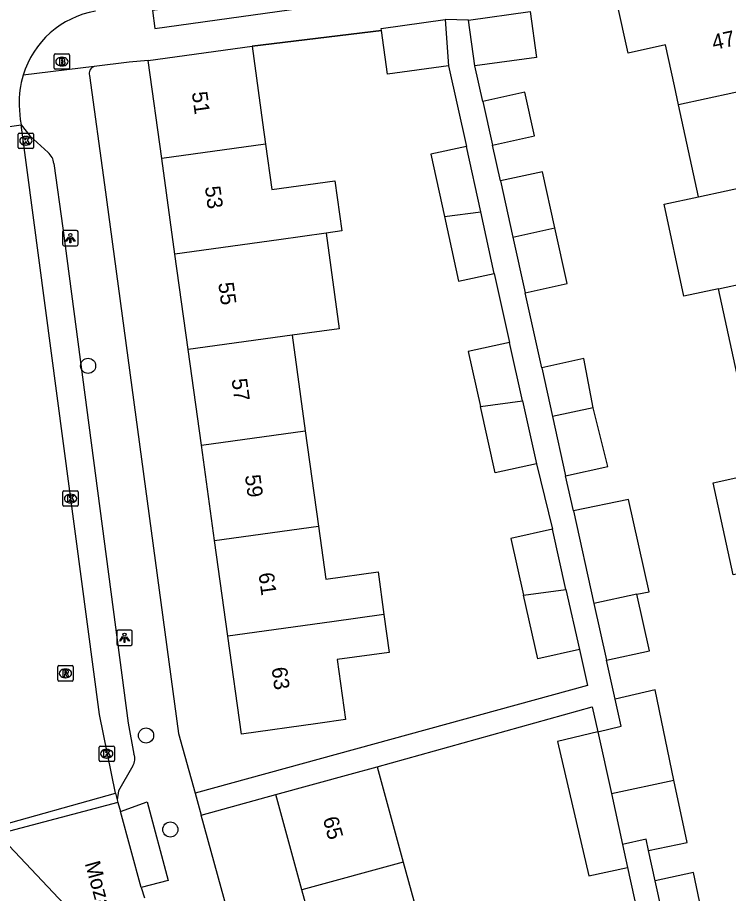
# Model space of a CAD drawing. Extents: x 159053 to 160041, y 380450 to 381422.
# Drawn here: x 159696.7 to 159742.8, y 380933.4 to 380990.2 of the extents above; entities that cross this region are included whole.
import ezdxf

# ---------------------------------------------------------------- set-up
doc = ezdxf.new("R2010")
doc.units = 0
for name, color, linetype in [('IMGEO_Boom', 7, 'Continuous'), ('IMGEO_Brandkraan', 7, 'Continuous'), ('IMGEO_Kolk', 7, 'Continuous'), ('IMGEO_Lichtpunt', 7, 'Continuous'), ('IMGEO_Muur', 7, 'Continuous'), ('IMGEO_Openbare_ruimte_label', 7, 'Continuous'), ('IMGEO_Pand', 7, 'Continuous'), ('IMGEO_Pand_nummerreeks', 7, 'Continuous'), ('IMGEO_Rijbaan_lokaal_open', 7, 'Continuous'), ('IMGEO_Rioolput', 7, 'Continuous'), ('IMGEO_Voetpad_op_trap', 7, 'Continuous'), ('IMGEO_Voetpad_open', 7, 'Continuous')]:
    doc.layers.add(name, color=color, linetype=linetype)

msp = doc.modelspace()

# ---------------------------------------------------------------- linework, layer by layer
at = {"layer": 'IMGEO_Boom'}
for centre in [(159701.274, 380967.567), (159705.031, 380943.603), (159706.604, 380937.507)]:
    msp.add_circle(centre, 0.489, dxfattribs=at)
at = {"layer": 'IMGEO_Brandkraan'}
for p, q in [((159699.148, 380987.793), (159700, 380987.793)), ((159699.073, 380986.867), (159699.073, 380987.719)), ((159699.561, 380987.573), (159699.586, 380987.573)), ((159700.074, 380987.719), (159700.074, 380986.867)), ((159700, 380986.793), (159699.148, 380986.793)), ((159699.584, 380987.013), (159699.559, 380987.013))]:
    msp.add_line(p, q, dxfattribs=at)
for points in [[(159699.148, 380987.793), (159700, 380987.793)], [(159699.073, 380986.867), (159699.073, 380987.719)], [(159699.421, 380987.493), (159699.421, 380987.093), (159699.634, 380987.093)], [(159699.652, 380987.493), (159699.421, 380987.493)], [(159699.6, 380987.412), (159699.546, 380987.412), (159699.546, 380987.336)], [(159699.546, 380987.336), (159699.599, 380987.336)], [(159699.608, 380987.26), (159699.546, 380987.26), (159699.546, 380987.179)], [(159699.546, 380987.179), (159699.608, 380987.179)], [(159700.074, 380987.719), (159700.074, 380986.867)], [(159700, 380986.793), (159699.148, 380986.793)]]:
    msp.add_lwpolyline(points, dxfattribs=at)
for centre, radius, start, end in [((159699.15, 380987.717), 0.0765, 91.552, 178.448), ((159699.15, 380987.717), 0.0765, 91.552, 178.448), ((159699.998, 380987.717), 0.0765, 1.552, 88.448), ((159699.998, 380987.717), 0.0765, 1.552, 88.448), ((159699.601, 380987.374), 0.0379, 267.8285, 90.9355), ((159699.609, 380987.219), 0.0404, 269.8759, 90.5077), ((159699.656, 380987.348), 0.145, 59.4692, 91.5367), ((159699.681, 380987.395), 0.0922, 285.5137, 58.1501), ((159699.686, 380987.203), 0.105, 301.3115, 78.989), ((159699.15, 380986.869), 0.0765, 181.552, 268.448), ((159699.15, 380986.869), 0.0765, 181.552, 268.448), ((159699.64, 380987.344), 0.251, 268.6676, 293.5347), ((159699.998, 380986.869), 0.0765, 271.552, 358.448), ((159699.998, 380986.869), 0.0765, 271.552, 358.448)]:
    msp.add_arc(centre, radius, start, end, dxfattribs=at)
for centre, major_axis, ratio, start_param, end_param in [((159699.56, 380987.293), (-0.387, 0.002), 0.722429, 4.712389, 7.853982), ((159699.585, 380987.293), (-0.39, 0.002), 0.717154, 1.570796, 4.712389)]:
    msp.add_ellipse(centre, major_axis=major_axis, ratio=ratio, start_param=start_param, end_param=end_param, dxfattribs=at)
at = {"layer": 'IMGEO_Kolk'}
for p, q in [((159696.813, 380982.66), (159697.665, 380982.66)), ((159696.738, 380981.734), (159696.738, 380982.586)), ((159697.226, 380982.44), (159697.251, 380982.44)), ((159697.739, 380982.586), (159697.739, 380981.734)), ((159697.665, 380981.66), (159696.813, 380981.66)), ((159697.249, 380981.88), (159697.224, 380981.88)), ((159699.635, 380958.538), (159699.635, 380959.39)), ((159699.71, 380959.464), (159700.562, 380959.464)), ((159700.636, 380959.39), (159700.636, 380958.538)), ((159700.123, 380959.244), (159700.148, 380959.244)), ((159700.562, 380958.464), (159699.71, 380958.464)), ((159700.146, 380958.684), (159700.121, 380958.684)), ((159702.056, 380942.921), (159702.908, 380942.921)), ((159701.981, 380941.995), (159701.981, 380942.847)), ((159702.469, 380942.701), (159702.494, 380942.701)), ((159702.982, 380942.847), (159702.982, 380941.995)), ((159702.908, 380941.921), (159702.056, 380941.921)), ((159702.492, 380942.141), (159702.467, 380942.141))]:
    msp.add_line(p, q, dxfattribs=at)
for points in [[(159696.813, 380982.66), (159697.665, 380982.66)], [(159696.738, 380981.734), (159696.738, 380982.586)], [(159697.059, 380982.36), (159697.182, 380982.36), (159697.182, 380982.209), (159697.312, 380982.36), (159697.476, 380982.36), (159697.33, 380982.209), (159697.483, 380981.96), (159697.331, 380981.96), (159697.246, 380982.124), (159697.182, 380982.057), (159697.182, 380981.96), (159697.059, 380981.96), (159697.059, 380982.36)], [(159697.739, 380982.586), (159697.739, 380981.734)], [(159697.665, 380981.66), (159696.813, 380981.66)], [(159699.635, 380958.538), (159699.635, 380959.39)], [(159699.71, 380959.464), (159700.562, 380959.464)], [(159700.636, 380959.39), (159700.636, 380958.538)], [(159699.956, 380959.164), (159700.079, 380959.164), (159700.079, 380959.013), (159700.209, 380959.164), (159700.373, 380959.164), (159700.227, 380959.013), (159700.38, 380958.764), (159700.228, 380958.764), (159700.143, 380958.928), (159700.079, 380958.861), (159700.079, 380958.764), (159699.956, 380958.764), (159699.956, 380959.164)], [(159700.562, 380958.464), (159699.71, 380958.464)], [(159702.056, 380942.921), (159702.908, 380942.921)], [(159701.981, 380941.995), (159701.981, 380942.847)], [(159702.302, 380942.621), (159702.425, 380942.621), (159702.425, 380942.47), (159702.555, 380942.621), (159702.719, 380942.621), (159702.573, 380942.47), (159702.726, 380942.221), (159702.574, 380942.221), (159702.489, 380942.385), (159702.425, 380942.318), (159702.425, 380942.221), (159702.302, 380942.221), (159702.302, 380942.621)], [(159702.982, 380942.847), (159702.982, 380941.995)], [(159702.908, 380941.921), (159702.056, 380941.921)]]:
    msp.add_lwpolyline(points, dxfattribs=at)
for centre, start, end in [((159696.815, 380982.584), 91.552, 178.448), ((159696.815, 380982.584), 91.552, 178.448), ((159697.663, 380982.584), 1.552, 88.448), ((159697.663, 380982.584), 1.552, 88.448), ((159696.815, 380981.736), 181.552, 268.448), ((159696.815, 380981.736), 181.552, 268.448), ((159697.663, 380981.736), 271.552, 358.448), ((159697.663, 380981.736), 271.552, 358.448), ((159699.712, 380959.388), 91.552, 178.448), ((159699.712, 380959.388), 91.552, 178.448), ((159700.56, 380959.388), 1.552, 88.448), ((159700.56, 380959.388), 1.552, 88.448), ((159699.712, 380958.54), 181.552, 268.448), ((159699.712, 380958.54), 181.552, 268.448), ((159700.56, 380958.54), 271.552, 358.448), ((159700.56, 380958.54), 271.552, 358.448), ((159702.058, 380942.845), 91.552, 178.448), ((159702.058, 380942.845), 91.552, 178.448), ((159702.906, 380942.845), 1.552, 88.448), ((159702.906, 380942.845), 1.552, 88.448), ((159702.058, 380941.997), 181.552, 268.448), ((159702.058, 380941.997), 181.552, 268.448), ((159702.906, 380941.997), 271.552, 358.448), ((159702.906, 380941.997), 271.552, 358.448)]:
    msp.add_arc(centre, 0.0765, start, end, dxfattribs=at)
for centre, major_axis, ratio, start_param, end_param in [((159697.225, 380982.16), (-0.387, 0.002), 0.722429, 4.712389, 7.853982), ((159697.25, 380982.16), (-0.39, 0.002), 0.717154, 1.570796, 4.712389), ((159700.122, 380958.964), (-0.387, 0.002), 0.722429, 4.712389, 7.853982), ((159700.147, 380958.964), (-0.39, 0.002), 0.717154, 1.570796, 4.712389), ((159702.468, 380942.421), (-0.387, 0.002), 0.722429, 4.712389, 7.853982), ((159702.493, 380942.421), (-0.39, 0.002), 0.717154, 1.570796, 4.712389)]:
    msp.add_ellipse(centre, major_axis=major_axis, ratio=ratio, start_param=start_param, end_param=end_param, dxfattribs=at)
at = {"layer": 'IMGEO_Lichtpunt'}
for p, q in [((159699.624, 380976.255), (159699.624, 380975.448)), ((159699.624, 380976.255), (159699.624, 380975.448)), ((159700.526, 380976.35), (159699.718, 380976.35)), ((159700.526, 380976.35), (159699.718, 380976.35)), ((159700.62, 380975.448), (159700.62, 380976.255)), ((159700.62, 380975.448), (159700.62, 380976.255)), ((159699.718, 380975.354), (159700.526, 380975.354)), ((159699.718, 380975.354), (159700.526, 380975.354)), ((159703.136, 380950.347), (159703.136, 380949.54)), ((159703.136, 380950.347), (159703.136, 380949.54)), ((159704.038, 380950.442), (159703.23, 380950.442)), ((159704.038, 380950.442), (159703.23, 380950.442)), ((159704.132, 380949.54), (159704.132, 380950.347)), ((159704.132, 380949.54), (159704.132, 380950.347)), ((159703.23, 380949.446), (159704.038, 380949.446)), ((159703.23, 380949.446), (159704.038, 380949.446))]:
    msp.add_line(p, q, dxfattribs=at)
for points in [[(159699.998, 380975.919), (159700.037, 380975.891), (159699.849, 380975.629), (159699.811, 380975.656), (159699.998, 380975.919)], [(159700.1, 380975.871), (159700.147, 380975.871), (159700.147, 380975.549), (159700.1, 380975.549), (159700.1, 380975.871)], [(159700.21, 380975.891), (159700.248, 380975.918), (159700.435, 380975.656), (159700.396, 380975.628), (159700.21, 380975.891)], [(159703.51, 380950.011), (159703.549, 380949.983), (159703.361, 380949.721), (159703.323, 380949.748), (159703.51, 380950.011)], [(159703.612, 380949.963), (159703.659, 380949.963), (159703.659, 380949.641), (159703.612, 380949.641), (159703.612, 380949.963)], [(159703.722, 380949.983), (159703.76, 380950.01), (159703.947, 380949.748), (159703.908, 380949.72), (159703.722, 380949.983)]]:
    msp.add_lwpolyline(points, dxfattribs=at)
for centre in [(159700.123, 380976.053), (159703.635, 380950.145)]:
    msp.add_circle(centre, 0.0994, dxfattribs=at)
for centre, start, end in [((159699.718, 380976.255), 90, 180), ((159699.718, 380976.255), 90, 180), ((159700.526, 380976.255), 0, 90), ((159700.526, 380976.255), 0, 90), ((159699.718, 380975.448), 180, 270), ((159699.718, 380975.448), 180, 270), ((159700.526, 380975.448), 270, 0), ((159700.526, 380975.448), 270, 360), ((159703.23, 380950.347), 90, 180), ((159703.23, 380950.347), 90, 180), ((159704.038, 380950.347), 0, 90), ((159704.038, 380950.347), 0, 90), ((159703.23, 380949.54), 180, 270), ((159703.23, 380949.54), 180, 270), ((159704.038, 380949.54), 270, 0), ((159704.038, 380949.54), 270, 360)]:
    msp.add_arc(centre, 0.0946, start, end, dxfattribs=at)
at = {"layer": 'IMGEO_Muur'}
msp.add_lwpolyline([(159711.9, 380988.291), (159720.286, 380989.3)], dxfattribs=at)
at = {"layer": 'IMGEO_Pand'}
for points in [[(159739.552, 380984.501), (159739.286, 380985.726), (159738.711, 380988.373), (159736.275, 380987.844), (159735.575, 380991.069)], [(159720.286, 380989.3), (159720.266, 380989.448), (159724.421, 380990.024)], [(159724.421, 380990.024), (159724.629, 380987.027)], [(159725.935, 380989.984), (159729.922, 380990.537)], [(159729.922, 380990.537), (159730.334, 380987.565), (159726.347, 380987.012)], [(159726.347, 380987.012), (159725.935, 380989.984)], [(159724.629, 380987.027), (159720.677, 380986.479), (159720.286, 380989.3)], [(159705.163, 380987.357), (159711.9, 380988.291)], [(159711.9, 380988.291), (159712.586, 380983.339), (159712.779, 380981.944)], [(159706.043, 380981.012), (159705.163, 380987.357)], [(159746.717, 380986.057), (159739.552, 380984.501)], [(159727.483, 380981.88), (159730.217, 380982.474), (159729.589, 380985.311), (159726.857, 380984.707)], [(159726.857, 380984.707), (159727.483, 380981.88)], [(159740.848, 380978.534), (159739.552, 380984.501)], [(159712.779, 380981.944), (159706.043, 380981.012)], [(159712.779, 380981.944), (159713.187, 380979.003), (159717.275, 380979.57), (159717.727, 380976.314), (159716.701, 380976.172)], [(159725.805, 380981.789), (159723.495, 380981.288), (159724.372, 380977.241)], [(159726.722, 380977.557), (159725.805, 380981.789)], [(159706.901, 380974.818), (159706.043, 380981.012)], [(159731.537, 380976.513), (159730.732, 380980.147), (159727.998, 380979.553)], [(159740.848, 380978.534), (159748.013, 380980.089)], [(159727.998, 380979.553), (159728.802, 380975.92)], [(159742.145, 380972.566), (159739.902, 380972.079), (159738.607, 380978.048), (159740.848, 380978.534)], [(159724.372, 380977.241), (159726.722, 380977.557)], [(159727.588, 380973.566), (159726.722, 380977.557)], [(159724.372, 380977.241), (159725.277, 380973.065), (159727.588, 380973.566)], [(159728.802, 380975.92), (159731.537, 380976.513)], [(159729.602, 380972.306), (159732.334, 380972.911), (159731.537, 380976.513)], [(159716.701, 380976.172), (159713.638, 380975.749), (159706.901, 380974.818)], [(159716.701, 380976.172), (159717.557, 380969.978), (159714.497, 380969.555)], [(159728.802, 380975.92), (159729.602, 380972.306)], [(159707.76, 380968.624), (159706.901, 380974.818)], [(159742.145, 380972.566), (159749.309, 380974.122)], [(159743.441, 380966.598), (159742.145, 380972.566)], [(159714.497, 380969.555), (159707.76, 380968.624)], [(159714.497, 380969.555), (159715.356, 380963.361)], [(159728.601, 380969.085), (159725.914, 380968.49), (159726.702, 380964.929)], [(159729.437, 380965.307), (159728.601, 380969.085)], [(159708.618, 380962.43), (159707.76, 380968.624)], [(159734.01, 380964.856), (159733.408, 380968.034), (159730.682, 380967.431)], [(159730.682, 380967.431), (159731.378, 380964.285)], [(159726.702, 380964.929), (159729.437, 380965.307)], [(159729.437, 380965.307), (159730.343, 380961.217)], [(159730.343, 380961.217), (159727.656, 380960.622), (159726.702, 380964.929)], [(159734.01, 380964.856), (159731.378, 380964.285)], [(159732.229, 380960.439), (159734.955, 380961.043), (159734.01, 380964.856)], [(159731.378, 380964.285), (159732.229, 380960.439)], [(159708.618, 380962.43), (159715.356, 380963.361)], [(159715.356, 380963.361), (159716.214, 380957.168)], [(159709.477, 380956.236), (159708.618, 380962.43)], [(159746.034, 380954.663), (159743.095, 380954.025), (159741.799, 380959.992), (159744.737, 380960.63)], [(159736.835, 380952.761), (159737.641, 380952.925), (159736.306, 380958.897), (159732.731, 380958.173)], [(159732.731, 380958.173), (159734.062, 380952.161)], [(159709.477, 380956.236), (159716.214, 380957.168)], [(159716.214, 380957.168), (159716.689, 380953.741), (159720.069, 380954.208), (159720.451, 380951.441)], [(159731.369, 380956.984), (159728.672, 380956.38), (159729.5, 380952.691)], [(159732.247, 380953.071), (159731.369, 380956.984)], [(159710.335, 380950.043), (159709.477, 380956.236)], [(159729.5, 380952.691), (159732.247, 380953.071)], [(159733.118, 380949.189), (159730.421, 380948.584), (159729.5, 380952.691)], [(159732.247, 380953.071), (159733.118, 380949.189)], [(159736.835, 380952.761), (159734.062, 380952.161)], [(159734.876, 380948.482), (159737.657, 380949.097), (159736.835, 380952.761)], [(159734.062, 380952.161), (159734.876, 380948.482)], [(159720.451, 380951.441), (159720.79, 380948.994), (159717.412, 380948.527), (159717.952, 380944.632), (159716.168, 380944.385), (159711.215, 380943.698), (159710.335, 380950.043)], [(159720.451, 380951.441), (159717.073, 380950.974), (159710.335, 380950.043)], [(159739.254, 380940.715), (159738.025, 380946.557), (159735.434, 380945.961)], [(159734.317, 380943.842), (159735.823, 380944.207), (159735.434, 380945.961)], [(159734.317, 380943.842), (159731.707, 380943.207), (159733.734, 380934.508), (159736.238, 380935.055)], [(159734.317, 380943.842), (159735.195, 380939.834)], [(159713.436, 380939.77), (159718.257, 380941.097), (159720.003, 380941.578)], [(159720.003, 380941.578), (159721.703, 380935.401)], [(159735.195, 380939.834), (159739.254, 380940.715)], [(159737.607, 380936.148), (159740.104, 380936.673), (159739.254, 380940.715)], [(159715.136, 380933.596), (159713.436, 380939.77)], [(159735.195, 380939.834), (159735.912, 380936.545)], [(159737.607, 380936.148), (159737.444, 380936.885), (159735.912, 380936.545)], [(159735.912, 380936.545), (159736.238, 380935.055)], [(159721.703, 380935.401), (159715.136, 380933.596)], [(159721.703, 380935.401), (159723.364, 380929.371)], [(159741.772, 380928.74), (159740.515, 380934.717), (159738.043, 380934.18)], [(159739.362, 380928.217), (159738.043, 380934.18)], [(159716.796, 380927.565), (159715.136, 380933.596)]]:
    msp.add_lwpolyline(points, dxfattribs=at)
at = {"layer": 'IMGEO_Rijbaan_lokaal_open'}
for points in [[(159696.805, 380984.452), (159696.873, 380983.547), (159696.938, 380983.189)], [(159692.329, 380982.539), (159696.938, 380983.189)], [(159703.047, 380939.869), (159702.009, 380944.971), (159696.938, 380983.189)], [(159695.017, 380937.616), (159703.047, 380939.869)], [(159703.047, 380939.869), (159703.16, 380939.431)], [(159703.204, 380939.257), (159695.431, 380937.204)], [(159703.16, 380939.431), (159703.204, 380939.257)], [(159703.204, 380939.257), (159703.364, 380938.667)], [(159704.723, 380933.738), (159703.364, 380938.667)], [(159700.436, 380931.909), (159695.431, 380937.204)], [(159704.723, 380933.738), (159704.926, 380933.073)]]:
    msp.add_lwpolyline(points, dxfattribs=at)
for centre, radius, start, end in [((159702.783, 380984.673), 5.982, 99.9432, 163.1371), ((159702.755, 380984.677), 5.954, 163.0959, 182.164)]:
    msp.add_arc(centre, radius, start, end, dxfattribs=at)
at = {"layer": 'IMGEO_Rioolput'}
for p, q in [((159699.305, 380947.205), (159699.305, 380948.057)), ((159699.38, 380948.131), (159700.232, 380948.131)), ((159700.306, 380948.057), (159700.306, 380947.205)), ((159699.793, 380947.911), (159699.818, 380947.911)), ((159700.232, 380947.131), (159699.38, 380947.131)), ((159699.816, 380947.351), (159699.791, 380947.351))]:
    msp.add_line(p, q, dxfattribs=at)
for points in [[(159699.305, 380947.205), (159699.305, 380948.057)], [(159699.38, 380948.131), (159700.232, 380948.131)], [(159700.306, 380948.057), (159700.306, 380947.205)], [(159699.894, 380947.829), (159699.642, 380947.831), (159699.642, 380947.431)], [(159699.642, 380947.431), (159699.766, 380947.431), (159699.766, 380947.593), (159699.777, 380947.593)], [(159699.82, 380947.75), (159699.766, 380947.75), (159699.766, 380947.669)], [(159699.766, 380947.669), (159699.818, 380947.669)], [(159699.824, 380947.564), (159699.895, 380947.431), (159700.035, 380947.431), (159699.97, 380947.557)], [(159700.232, 380947.131), (159699.38, 380947.131)]]:
    msp.add_lwpolyline(points, dxfattribs=at)
for centre, radius, start, end in [((159699.382, 380948.055), 0.0765, 91.552, 178.448), ((159699.382, 380948.055), 0.0765, 91.552, 178.448), ((159700.23, 380948.055), 0.0765, 1.552, 88.448), ((159700.23, 380948.055), 0.0765, 1.552, 88.448), ((159699.776, 380947.54), 0.0533, 26.0293, 88.6989), ((159699.802, 380947.858), 0.19, 274.7715, 282.9687), ((159699.826, 380947.654), 0.0964, 77.0061, 93.1865), ((159699.84, 380947.711), 0.0378, 276.6634, 79.6772), ((159699.893, 380947.719), 0.109, 350.3612, 89.416), ((159699.891, 380947.719), 0.112, 277.5842, 350.9817), ((159699.875, 380947.504), 0.108, 29.5134, 73.7905), ((159699.382, 380947.207), 0.0765, 181.552, 268.448), ((159699.382, 380947.207), 0.0765, 181.552, 268.448), ((159700.23, 380947.207), 0.0765, 271.552, 358.448), ((159700.23, 380947.207), 0.0765, 271.552, 358.448)]:
    msp.add_arc(centre, radius, start, end, dxfattribs=at)
for centre, major_axis, ratio, start_param, end_param in [((159699.792, 380947.631), (-0.387, 0.002), 0.722429, 4.712389, 7.853982), ((159699.817, 380947.631), (-0.39, 0.002), 0.717154, 1.570796, 4.712389)]:
    msp.add_ellipse(centre, major_axis=major_axis, ratio=ratio, start_param=start_param, end_param=end_param, dxfattribs=at)
at = {"layer": 'IMGEO_Voetpad_op_trap'}
for points in [[(159701.36, 380986.388), (159702.337, 380979.302), (159707.142, 380943.733), (159708.209, 380939.854)], [(159696.938, 380983.189), (159697.493, 380982.475), (159698.68, 380981.401)], [(159699.057, 380980.695), (159699.64, 380976.485), (159703.872, 380944.393), (159704.247, 380942.399)], [(159704.168, 380941.639), (159703.251, 380940.013), (159703.16, 380939.431)], [(159703.364, 380938.667), (159705.113, 380939.298), (159706.467, 380934.204), (159704.723, 380933.738)], [(159724.672, 380880.027), (159708.598, 380938.439)]]:
    msp.add_lwpolyline(points, dxfattribs=at)
for centre, radius, start, end in [((159701.786, 380986.532), 0.45, 103.9133, 198.6169), ((159697.993, 380980.581), 1.07, 6.1403, 50.0636), ((159703.547, 380942.088), 0.766, 324.1428, 23.9884)]:
    msp.add_arc(centre, radius, start, end, dxfattribs=at)
at = {"layer": 'IMGEO_Voetpad_open'}
for points in [[(159717.575, 380991.103), (159717.413, 380992.266), (159705.439, 380990.598), (159705.601, 380989.435), (159717.575, 380991.103)], [(159725.935, 380989.984), (159724.421, 380990.024)], [(159720.286, 380989.3), (159711.9, 380988.291)], [(159705.163, 380987.357), (159703.94, 380987.255), (159701.678, 380986.968)], [(159701.678, 380986.968), (159697.058, 380986.408)], [(159724.629, 380987.027), (159725.805, 380981.789)], [(159726.857, 380984.707), (159726.347, 380987.012)], [(159727.998, 380979.553), (159727.483, 380981.88)], [(159727.588, 380973.566), (159728.601, 380969.085)], [(159730.682, 380967.431), (159729.602, 380972.306)], [(159730.343, 380961.217), (159731.369, 380956.984)], [(159732.731, 380958.173), (159732.229, 380960.439)], [(159733.118, 380949.189), (159733.642, 380946.852), (159708.209, 380939.854)], [(159735.434, 380945.961), (159734.876, 380948.482)], [(159720.003, 380941.578), (159733.956, 380945.453), (159734.317, 380943.842)], [(159708.209, 380939.854), (159708.598, 380938.439)], [(159708.598, 380938.439), (159713.436, 380939.77)], [(159738.043, 380934.18), (159737.607, 380936.148)], [(159736.238, 380935.055), (159737.141, 380930.921)]]:
    msp.add_lwpolyline(points, dxfattribs=at)

# ---------------------------------------------------------------- texts
at = {"layer": 'IMGEO_Openbare_ruimte_label'}
msp.add_text('Mozartlaan', height=1, rotation=285.5517, dxfattribs=at).set_placement((159701.051, 380935.314))
at = {"layer": 'IMGEO_Pand_nummerreeks'}
for s, rotation, p in [('47', 12.251, (159741.831, 380988.038)), ('51', 277.892, (159707.994, 380985.291)), ('53', 277.8894, (159708.841, 380979.166)), ('55', 277.892, (159709.707, 380972.929)), ('57', 277.892, (159710.572, 380966.692)), ('59', 277.892, (159711.436, 380960.455)), ('61', 277.8894, (159712.316, 380954.106)), ('63', 277.8894, (159713.164, 380947.981)), ('65', 285.3914, (159716.48, 380938.204))]:
    msp.add_text(s, height=1, rotation=rotation, dxfattribs=at).set_placement(p)

doc.saveas('drawing.dxf')
